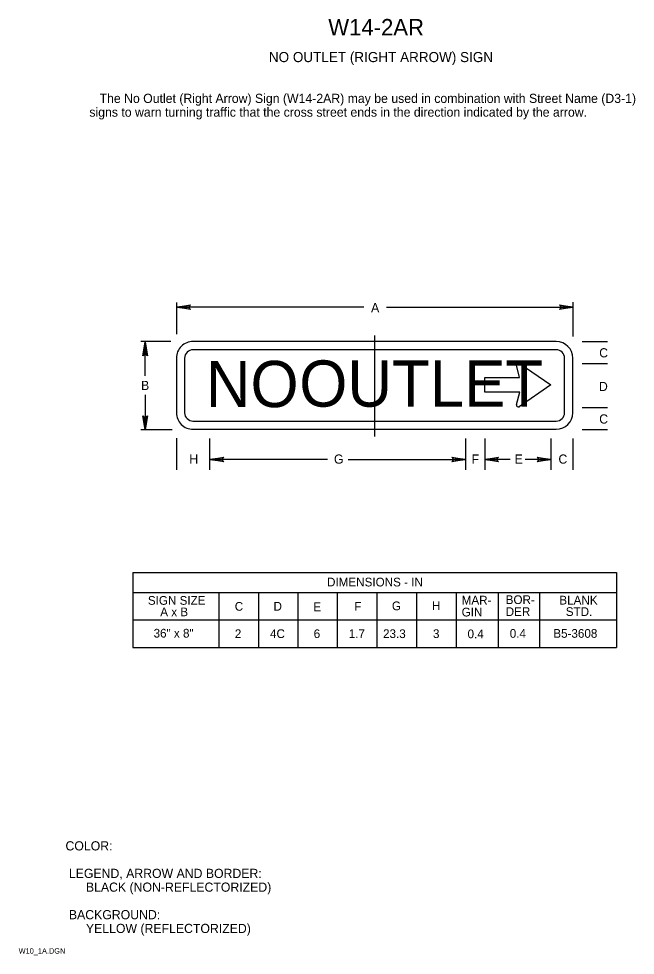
# Model space of a CAD drawing. Extents: x 0.013 to 0.181, y 0.004 to 0.259.
import ezdxf

# ---------------------------------------------------------------- set-up
doc = ezdxf.new("R2010")
doc.units = 0
for name, color, linetype in [('1', 7, 'Continuous'), ('2', 7, 'Continuous'), ('3', 7, 'Continuous')]:
    doc.layers.add(name, color=color, linetype=linetype)

# ---------------------------------------------------------------- blocks, each defined once
blk = doc.blocks.new('RARROW')
at = {"layer": '3'}
for p, q in [((-2.156, 0.28500000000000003), (-2.2665, 0.384625)), ((-2.2665, 0.384625), (0, 0)), ((0, 0), (-2.2665, -0.379125)), ((-2.156, 0.28500000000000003), (-2.075625, 0.12075)), ((0, 0), (-2.156, 0.28500000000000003)), ((-2.14975, -0.2705), (0, 0)), ((-2.075625, 0.12075), (0, 0)), ((0, 0), (-2.074, -0.108)), ((-2.2665, -0.379125), (-2.14975, -0.2705)), ((-2.074, -0.108), (-2.14975, -0.2705))]:
    blk.add_line(p, q, dxfattribs=at)

msp = doc.modelspace()

# ---------------------------------------------------------------- linework, layer by layer
at = {"layer": '1'}
msp.add_line((0.10961895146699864, 0.17275000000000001), (0.10961895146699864, 0.14523299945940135), dxfattribs=at)
at = {"layer": '3'}
for p, q in [((0.055725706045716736, 0.173125), (0.055725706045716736, 0.18174713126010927)), ((0.16373811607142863, 0.1725172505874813), (0.16373811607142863, 0.18188938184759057)), ((0.1066937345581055, 0.18049713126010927), (0.05576086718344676, 0.18049713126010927)), ((0.11287659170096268, 0.18049713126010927), (0.16372946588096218, 0.18049713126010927)), ((0.05409428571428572, 0.17112213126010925), (0.04588586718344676, 0.17112213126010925)), ((0.04713586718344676, 0.16175542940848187), (0.04713586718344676, 0.17112213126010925)), ((0.15914361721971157, 0.171125), (0.06009428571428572, 0.171125)), ((0.16620796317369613, 0.171125), (0.17308296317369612, 0.171125)), ((0.15914361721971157, 0.168875), (0.06009428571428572, 0.168875)), ((0.05559428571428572, 0.166625), (0.05559428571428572, 0.15172487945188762)), ((0.057844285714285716, 0.166625), (0.057844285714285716, 0.15172487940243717)), ((0.16139361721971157, 0.15172874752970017), (0.16139361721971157, 0.16662886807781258)), ((0.16364361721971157, 0.15172874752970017), (0.16364361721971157, 0.16662886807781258)), ((0.14909065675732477, 0.16129900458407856), (0.1483088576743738, 0.16468732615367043)), ((0.14901926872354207, 0.16522009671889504), (0.1576325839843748, 0.15935906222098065)), ((0.16620796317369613, 0.165125), (0.17308296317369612, 0.165125)), ((0.13964361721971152, 0.16129965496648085), (0.14909065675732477, 0.16129900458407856)), ((0.13964361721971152, 0.15733089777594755), (0.13964361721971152, 0.16129965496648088)), ((0.1576325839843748, 0.15935906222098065), (0.14906326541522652, 0.15336541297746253)), ((0.04713586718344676, 0.15662658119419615), (0.04713586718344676, 0.14722201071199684)), ((0.14919477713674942, 0.15733089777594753), (0.13964361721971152, 0.15733089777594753)), ((0.14830849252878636, 0.15394263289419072), (0.14919477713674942, 0.15733089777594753)), ((0.16620796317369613, 0.153125), (0.17308296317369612, 0.153125)), ((0.06009428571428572, 0.1494748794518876), (0.15914361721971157, 0.1494748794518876)), ((0.05446928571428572, 0.14712213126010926), (0.04588586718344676, 0.14712213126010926)), ((0.05446928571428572, 0.14712213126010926), (0.04588586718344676, 0.14712213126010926)), ((0.06009428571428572, 0.14722487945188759), (0.15914361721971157, 0.14722487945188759)), ((0.16620796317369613, 0.147125), (0.17308296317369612, 0.147125)), ((0.055639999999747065, 0.14478244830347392), (0.055639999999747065, 0.13619902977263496)), ((0.06464361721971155, 0.1447301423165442), (0.06464361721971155, 0.13619902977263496)), ((0.13439361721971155, 0.1447301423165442), (0.13439361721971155, 0.13619902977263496)), ((0.13964361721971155, 0.1447301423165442), (0.13964361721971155, 0.13619902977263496)), ((0.15764361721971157, 0.1447301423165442), (0.15764361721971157, 0.13619902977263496)), ((0.16364361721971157, 0.1447301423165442), (0.16364361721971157, 0.13619902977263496)), ((0.09679944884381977, 0.13896441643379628), (0.06467031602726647, 0.13896441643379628)), ((0.10239944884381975, 0.13896441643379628), (0.13439361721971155, 0.13896441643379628)), ((0.1465565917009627, 0.13896441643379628), (0.13964361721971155, 0.13896441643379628)), ((0.15764361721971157, 0.13896441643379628), (0.15064802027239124, 0.13896441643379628)), ((0.043705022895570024, 0.10817070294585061), (0.17553288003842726, 0.10817070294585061)), ((0.043705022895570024, 0.10817070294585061), (0.043705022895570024, 0.08779570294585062)), ((0.17553288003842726, 0.10817070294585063), (0.17553288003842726, 0.08779570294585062)), ((0.043705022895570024, 0.10279570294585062), (0.17553288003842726, 0.10279570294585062)), ((0.06720502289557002, 0.10279570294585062), (0.06720502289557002, 0.08779570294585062)), ((0.07795502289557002, 0.10279570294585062), (0.07795502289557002, 0.08779570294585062)), ((0.08870502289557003, 0.10279570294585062), (0.08870502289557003, 0.08779570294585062)), ((0.09945502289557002, 0.10279570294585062), (0.09945502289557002, 0.08779570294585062)), ((0.11020502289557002, 0.10279570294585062), (0.11020502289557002, 0.08779570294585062)), ((0.12108002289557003, 0.10279570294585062), (0.12108002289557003, 0.08779570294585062)), ((0.13183002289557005, 0.10279570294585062), (0.13183002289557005, 0.08779570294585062)), ((0.14326428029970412, 0.10279570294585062), (0.14326428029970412, 0.08779570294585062)), ((0.1545968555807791, 0.10279570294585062), (0.1545968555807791, 0.08779570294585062)), ((0.043705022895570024, 0.09529570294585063), (0.17553288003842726, 0.09529570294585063)), ((0.043705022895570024, 0.08779570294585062), (0.17553288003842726, 0.08779570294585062))]:
    msp.add_line(p, q, dxfattribs=at)
for centre, radius, start, end in [((0.06012654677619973, 0.1665966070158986), 0.004532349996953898, 89.64106666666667, 179.6410666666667), ((0.15914361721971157, 0.1666288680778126), 0.0045000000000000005, 0, 90), ((0.06012654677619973, 0.1665966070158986), 0.0022824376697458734, 89.28723611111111, 179.2872361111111), ((0.15914361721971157, 0.1666288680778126), 0.0022500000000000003, 0, 90), ((0.14877666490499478, 0.16480051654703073), 0.00048130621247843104, 59.54676398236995, 193.60184176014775), ((0.14881158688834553, 0.15381844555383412), 0.0005181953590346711, 166.1339084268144, 300.1676695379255), ((0.06012267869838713, 0.1517571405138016), 0.004528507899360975, 180.4081777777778, 270.40817777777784), ((0.06012267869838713, 0.1517571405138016), 0.002278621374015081, 180.81123055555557, 270.81123055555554), ((0.15914361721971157, 0.15172874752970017), 0.0045000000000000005, 270, 0), ((0.15914361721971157, 0.15172874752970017), 0.0022500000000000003, 270, 0)]:
    msp.add_arc(centre, radius, start, end, dxfattribs=at)

# ---------------------------------------------------------------- block references
at = {"layer": '3', "xscale": 0.0016545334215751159, "yscale": 0.0016366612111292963}
for p in [(0.16373033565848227, 0.1805172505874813), (0.13439361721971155, 0.13896441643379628), (0.15764361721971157, 0.13896441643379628)]:
    msp.add_blockref('RARROW', p, dxfattribs=at)
for p, rotation in [((0.05571928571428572, 0.1805), 180), ((0.04709428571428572, 0.171), 90), ((0.04709428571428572, 0.14709987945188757), -90), ((0.06475373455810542, 0.13896728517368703), 180), ((0.1396371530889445, 0.13896728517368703), 180)]:
    msp.add_blockref('RARROW', p, dxfattribs=dict(at, rotation=rotation))

# ---------------------------------------------------------------- texts
at = {"layer": '1'}
for s, height, p in [('W14-2AR', 0.0045000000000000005, (0.09699590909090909, 0.2545)), ('NO OUTLET (RIGHT ARROW) SIGN', 0.00275025, (0.08081261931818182, 0.24725)), ('COLOR:', 0.0024997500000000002, (0.025375, 0.032499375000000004)), (' LEGEND, ARROW AND BORDER:', 0.0024997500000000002, (0.025375, 0.024999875)), ('      BLACK (NON-REFLECTORIZED)', 0.0024997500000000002, (0.025375, 0.021250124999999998)), (' BACKGROUND:', 0.0024997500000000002, (0.025375, 0.013750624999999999)), ('      YELLOW (REFLECTORIZED)', 0.0024997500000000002, (0.025375, 0.010000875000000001)), ('W10_1A.DGN', 0.0015, (0.012625, 0.004375))]:
    msp.add_text(s, height=height, dxfattribs=at).set_placement(p)
at = {"layer": '2'}
for s, p in [('   The No Outlet (Right Arrow) Sign (W14-2AR) may be used in combination with Street Name (D3-1) ', (0.03187847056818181, 0.23612525)), ('signs to warn turning traffic that the cross street ends in the direction indicated by the arrow.', (0.03187847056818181, 0.23237549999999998))]:
    msp.add_text(s, height=0.0024997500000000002, dxfattribs=at).set_placement(p)
at = {"layer": '3'}
for s, height, p in [('A', 0.0024997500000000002, (0.10866298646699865, 0.179125)), ('C', 0.0024997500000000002, (0.17083296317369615, 0.16681080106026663)), ('NO', 0.0126, (0.0636327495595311, 0.15326217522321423)), ('OUTLET', 0.0126, (0.08909693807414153, 0.15338666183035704)), ('B', 0.0024997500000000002, (0.04596928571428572, 0.1579250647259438)), ('D', 0.0024997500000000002, (0.17076137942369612, 0.15764858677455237)), ('C', 0.0024997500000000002, (0.17083296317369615, 0.14878514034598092)), ('H', 0.0024997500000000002, (0.05913428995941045, 0.13785942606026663)), ('G', 0.0024997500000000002, (0.09855091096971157, 0.13785942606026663)), ('F', 0.0024997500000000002, (0.13604727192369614, 0.13785942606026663)), ('E', 0.0024997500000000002, (0.14775885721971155, 0.13785942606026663)), ('C', 0.0024997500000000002, (0.15972439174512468, 0.13785942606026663)), ('DIMENSIONS - IN', 0.0023752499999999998, (0.09666124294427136, 0.10442070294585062)), ('SIGN SIZE', 0.0023752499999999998, (0.04783002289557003, 0.09942070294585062)), ('C', 0.0023752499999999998, (0.07150814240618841, 0.09779570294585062)), ('D', 0.0023752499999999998, (0.08208002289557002, 0.09782688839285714)), ('E', 0.0023752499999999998, (0.09290002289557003, 0.09767070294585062)), ('F', 0.0023752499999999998, (0.10408002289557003, 0.09779570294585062)), ('G', 0.0023752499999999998, (0.11434288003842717, 0.09793421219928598)), ('H', 0.0023752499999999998, (0.1252581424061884, 0.09802418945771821)), ('MAR-', 0.0023752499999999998, (0.13334707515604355, 0.09949533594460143)), ('BOR-', 0.0023752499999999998, (0.14534707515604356, 0.09962033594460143)), ('BLANK', 0.0023752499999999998, (0.1599720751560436, 0.09949533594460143)), ('A x B', 0.0023752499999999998, (0.051205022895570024, 0.09629570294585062)), ('GIN', 0.0023752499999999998, (0.13334707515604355, 0.09624533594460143)), ('DER', 0.0023752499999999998, (0.14534707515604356, 0.09637033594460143)), ('STD.', 0.0023752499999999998, (0.16172207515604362, 0.09637033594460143)), ('36" x 8"', 0.0023752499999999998, (0.049386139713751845, 0.09048307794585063)), ('2', 0.0023752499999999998, (0.07152855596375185, 0.09035807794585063)), ('4C', 0.0023752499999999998, (0.08111960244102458, 0.09035807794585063)), ('6', 0.0023752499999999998, (0.0930242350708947, 0.09035807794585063)), ('1.7', 0.0023752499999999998, (0.10257509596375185, 0.09035807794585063)), ('23.3', 0.0023752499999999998, (0.11192237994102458, 0.09035807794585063)), ('3', 0.0023752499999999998, (0.12552521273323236, 0.09035807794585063)), ('0.4', 0.0023752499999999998, (0.13495407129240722, 0.09030771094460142)), ('0.4', 0.0023752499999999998, (0.1464540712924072, 0.09043271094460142)), ('B5-3608', 0.0023752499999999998, (0.15831650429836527, 0.09043271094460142))]:
    msp.add_text(s, height=height, dxfattribs=at).set_placement(p)

doc.saveas('drawing.dxf')
